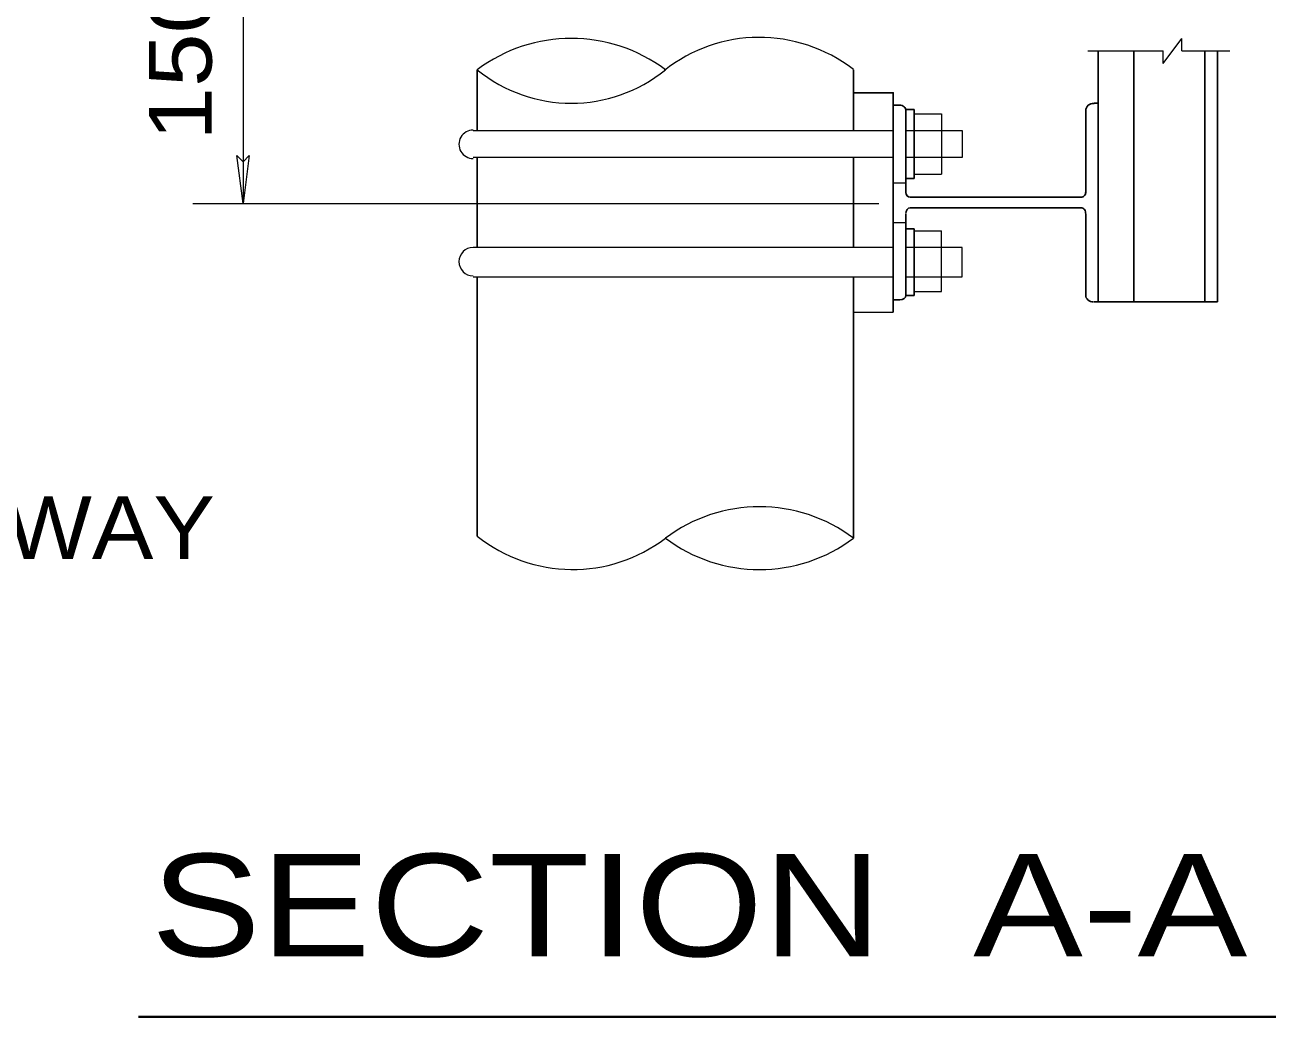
# Model space of a CAD drawing. Extents: x 312601.858 to 312602.699, y 144420.109 to 144420.704.
# Drawn here: x 312602.1613 to 312602.2211, y 144420.4567 to 144420.5041 of the extents above; entities that cross this region are included whole.
import ezdxf
from ezdxf.enums import TextEntityAlignment as Align

# ---------------------------------------------------------------- set-up
doc = ezdxf.new("R2010")
doc.units = 0
doc.header["$LTSCALE"] = 0.0012
doc.linetypes.add('DOT_DASHED', pattern=[7.7, 5, -1.2, 0.3, -1.2])
doc.linetypes.add('MEDIUM_DASHED', pattern=[4.5, 3, -1.5])
doc.layers.add('1', color=7, linetype='Continuous', lineweight=13)
doc.layers.add('2', color=7, linetype='Continuous', lineweight=13)

msp = doc.modelspace()

# ---------------------------------------------------------------- linework, layer by layer
at = {"layer": '1'}
for p, q in [((312602.1717, 144420.5139), (312602.1717, 144420.4956)), ((312602.2157, 144420.5023), (312602.2166, 144420.5035)), ((312602.2166, 144420.5029), (312602.2166, 144420.5035)), ((312602.2121, 144420.5029), (312602.2157, 144420.5029)), ((312602.2157, 144420.5023), (312602.2157, 144420.5029)), ((312602.2166, 144420.5029), (312602.2189, 144420.5029)), ((312602.2028, 144420.5009), (312602.2028, 144420.492)), ((312602.1827, 144420.4991), (312602.2009, 144420.4991)), ((312602.2051, 144420.4991), (312602.2061, 144420.4991)), ((312602.2061, 144420.4991), (312602.2061, 144420.4978)), ((312602.2009, 144420.4978), (312602.1827, 144420.4978)), ((312602.2061, 144420.4978), (312602.2051, 144420.4978)), ((312602.2038, 144420.497), (312602.2051, 144420.497)), ((312602.2028, 144420.4966), (312602.2034, 144420.4966)), ((312602.1693, 144420.4956), (312602.2021, 144420.4956)), ((312602.2028, 144420.4947), (312602.2034, 144420.4947)), ((312602.2038, 144420.4943), (312602.2051, 144420.4943)), ((312602.2051, 144420.4914), (312602.2051, 144420.4943)), ((312602.2009, 144420.4935), (312602.1827, 144420.4935)), ((312602.2061, 144420.4935), (312602.2051, 144420.4935)), ((312602.2061, 144420.4921), (312602.2061, 144420.4935)), ((312602.1827, 144420.4921), (312602.2009, 144420.4921)), ((312602.2051, 144420.4921), (312602.2061, 144420.4921)), ((312602.2038, 144420.4914), (312602.2051, 144420.4914)), ((312602.2009, 144420.4904), (312602.2028, 144420.4904))]:
    msp.add_line(p, q, dxfattribs=at)
at = {"layer": '1', "lineweight": 25}
for p, q in [((312602.2126, 144420.5029), (312602.2126, 144420.4909)), ((312602.2143, 144420.5029), (312602.2143, 144420.4909)), ((312602.2177, 144420.5029), (312602.2177, 144420.4909)), ((312602.2183, 144420.5029), (312602.2183, 144420.4909)), ((312602.1829, 144420.502), (312602.1829, 144420.4991)), ((312602.2009, 144420.502), (312602.2009, 144420.4991)), ((312602.2028, 144420.5003), (312602.2031, 144420.5003)), ((312602.2034, 144420.5001), (312602.2034, 144420.4961)), ((312602.2034, 144420.5001), (312602.2038, 144420.5001)), ((312602.2038, 144420.5001), (312602.2038, 144420.4968)), ((312602.212, 144420.5001), (312602.212, 144420.4961)), ((312602.2124, 144420.5004), (312602.2126, 144420.5004)), ((312602.1829, 144420.4978), (312602.1829, 144420.4935)), ((312602.2009, 144420.4978), (312602.2009, 144420.4935)), ((312602.2034, 144420.4968), (312602.2038, 144420.4968)), ((312602.2036, 144420.4959), (312602.2118, 144420.4959)), ((312602.2034, 144420.4951), (312602.2034, 144420.4912)), ((312602.2036, 144420.4954), (312602.2118, 144420.4954)), ((312602.212, 144420.4951), (312602.212, 144420.4912)), ((312602.2034, 144420.4944), (312602.2038, 144420.4944)), ((312602.2038, 144420.4944), (312602.2038, 144420.4912)), ((312602.1829, 144420.4921), (312602.1829, 144420.4797)), ((312602.2009, 144420.4921), (312602.2009, 144420.4796)), ((312602.2028, 144420.491), (312602.2031, 144420.491)), ((312602.2034, 144420.4912), (312602.2038, 144420.4912)), ((312602.2124, 144420.4909), (312602.2126, 144420.4909)), ((312602.2126, 144420.4909), (312602.2183, 144420.4909))]:
    msp.add_line(p, q, dxfattribs=at)
at = {"layer": '1', "linetype": 'MEDIUM_DASHED'}
for p, q in [((312602.2009, 144420.4991), (312602.2028, 144420.4991)), ((312602.2034, 144420.4991), (312602.2051, 144420.4991)), ((312602.2028, 144420.4978), (312602.2009, 144420.4978)), ((312602.2051, 144420.4978), (312602.2034, 144420.4978)), ((312602.2028, 144420.4935), (312602.2009, 144420.4935)), ((312602.2051, 144420.4935), (312602.2034, 144420.4935)), ((312602.2009, 144420.4921), (312602.2028, 144420.4921)), ((312602.2034, 144420.4921), (312602.2051, 144420.4921))]:
    msp.add_line(p, q, dxfattribs=at)
at = {"layer": '1', "lineweight": 25}
msp.add_lwpolyline([(312602.2009, 144420.5009), (312602.2028, 144420.5009), (312602.2028, 144420.4904)], dxfattribs=at)
at = {"layer": '1'}
msp.add_lwpolyline([(312602.2038, 144420.4999), (312602.2051, 144420.4999), (312602.2051, 144420.497)], dxfattribs=at)
msp.add_lwpolyline([(312602.172, 144420.4979), (312602.1717, 144420.4956), (312602.1714, 144420.4979), (312602.1717, 144420.4976)], close=True, dxfattribs=at)
for centre, radius, start, end in [((312602.1874, 144420.496), 0.0075, 53.1301, 126.8699), ((312602.1874, 144420.507525), 0.007126, 230.83789, 309.16211), ((312602.182705, 144420.498435), 0.00068, 89.99844, 269.99844), ((312602.182705, 144420.492825), 0.00068, 90.00156, 270), ((312602.1964, 144420.473603), 0.007497, 53.11482, 126.88518), ((312602.187464, 144420.485409), 0.007309, 231.35969, 307.36712), ((312602.1964, 144420.485597), 0.007497, 233.11482, 306.88518)]:
    msp.add_arc(centre, radius, start, end, dxfattribs=at)
msp.add_ellipse((312602.196464, 144420.496199), major_axis=(-0.004613, 0.005762), ratio=0.989423, start_param=4.955214, end_param=6.283185, dxfattribs=at)
at = {"layer": '1', "lineweight": 25}
for centre, major_axis, ratio, start_param, end_param in [((312602.203105, 144420.50005), (0.000295, 0), 0.864407, 6.283185, 7.853982), ((312602.21237, 144420.50005), (-0.00037, 0), 0.918919, 4.633787, 6.283185), ((312602.203615, 144420.49614), (0, -0.00024), 0.895833, 4.712389, 6.283185), ((312602.211775, 144420.49614), (0, -0.00024), 0.9375, 6.283185, 7.853982), ((312602.203615, 144420.49512), (0, -0.00028), 0.767857, 3.141593, 4.712389), ((312602.211775, 144420.49512), (0, 0.00028), 0.803571, 4.634118, 6.283185), ((312602.203105, 144420.49121), (0.000295, 0), 0.711864, 4.712389, 6.283185), ((312602.21237, 144420.49121), (-0.00037, 0), 0.837838, 6.283185, 7.853982)]:
    msp.add_ellipse(centre, major_axis=major_axis, ratio=ratio, start_param=start_param, end_param=end_param, dxfattribs=at)
at = {"layer": '2', "linetype": 'DOT_DASHED'}
msp.add_line((312602.1919, 144420.6459), (312602.1919, 144420.4762), dxfattribs=at)
at = {"layer": '2', "lineweight": 40}
msp.add_line((312602.1667, 144420.4567), (312602.2211, 144420.4567), dxfattribs=at)

# ---------------------------------------------------------------- texts
at = {"layer": '2', "width": 1.15}
msp.add_text('1500 MM (MAX)', height=0.003, rotation=90, dxfattribs=at).set_placement((312602.1702, 144420.5154), align=Align.CENTER)
at = {"layer": '2'}
for s, height, width, p in [('LUMINAIRE AND WALKWAY', 0.003, 1.1, (312602.112, 144420.4786)), ('SECTION  A-A', 0.0049, 1.2, (312602.1673, 144420.4596))]:
    msp.add_text(s, height=height, dxfattribs=dict(at, width=width)).set_placement(p)

doc.saveas('drawing.dxf')
